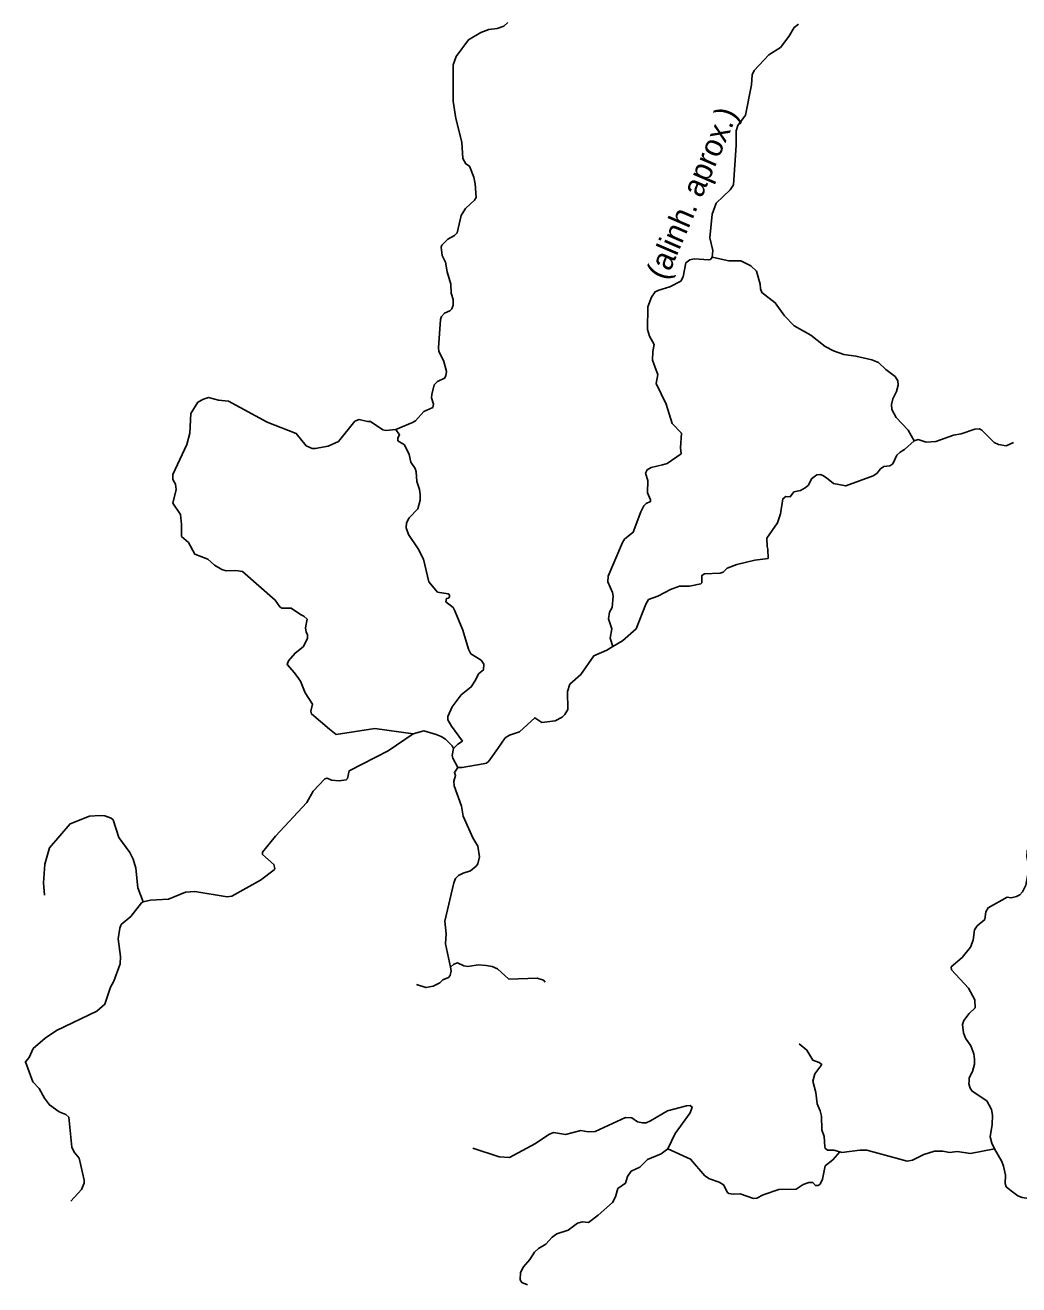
# Model space of a CAD drawing. Extents: x 332 to 501, y 9447 to 9559.
# Drawn here: x 427.75 to 444.61, y 9511.96 to 9533.34 of the extents above; entities that cross this region are included whole.
import ezdxf

# ---------------------------------------------------------------- set-up
doc = ezdxf.new("R2010")
doc.units = 0
for name, color, linetype in [('Level 31', 7, 'Continuous'), ('Level 5', 7, 'Continuous'), ('Level 6', 7, 'Continuous'), ('Level 7', 7, 'Continuous')]:
    doc.layers.add(name, color=color, linetype=linetype)

msp = doc.modelspace()

# ---------------------------------------------------------------- linework, layer by layer
at = {"layer": 'Level 5'}
for points in [[(435.3981, 9530.4192), (435.3855, 9530.6514), (435.3615, 9530.7649), (435.2848, 9530.9504), (435.2256, 9530.9888), (435.1712, 9531.0831), (435.1588, 9531.3603), (435.0561, 9531.7611), (435.0109, 9532.0528), (435.0114, 9532.6725), (435.0625, 9532.8116), (435.272, 9533.0962), (435.4783, 9533.2193), (435.6142, 9533.2689), (435.7565, 9533.2897), (435.8684, 9533.3265), (435.9372, 9533.392)], [(440.8715, 9533.3618), (440.7932, 9533.3049), (440.7043, 9533.1511), (440.5631, 9532.9666), (440.3647, 9532.8404), (440.1169, 9532.5734), (440.0833, 9532.503), (440.0705, 9532.3303), (439.9706, 9531.8193), (439.8404, 9531.6404), (439.8116, 9531.5481), (439.8131, 9531.307), (439.7667, 9530.6354), (439.7091, 9530.5507), (439.4725, 9530.3252), (439.4021, 9530.1365), (439.3669, 9529.7336), (439.4158, 9529.5186), (439.4053, 9529.4058)], [(435.0089, 9528.6887), (434.9746, 9528.7966), (434.9698, 9528.9501), (434.9064, 9529.1581), (434.88, 9529.32), (434.8246, 9529.4335), (434.8067, 9529.5753), (434.8195, 9529.6073), (434.9202, 9529.7112), (435.0306, 9529.7726), (435.0793, 9529.8183), (435.1463, 9530.1146), (435.2192, 9530.2293), (435.3711, 9530.3716), (435.3981, 9530.4192)], [(439.1012, 9529.3791), (439.028, 9529.3626), (438.9592, 9529.3115), (438.9106, 9529.0735), (438.8727, 9528.9973), (438.6858, 9528.9005), (438.4979, 9528.8473)], [(439.3751, 9529.3684), (439.3494, 9529.3578), (439.1012, 9529.3791)], [(439.4053, 9529.4058), (439.3751, 9529.3684)], [(438.4979, 9528.8473), (438.4347, 9528.819), (438.3756, 9528.7262), (438.3132, 9528.5631), (438.3084, 9528.1794), (438.3404, 9528.0643), (438.4201, 9527.9247), (438.3964, 9527.8068), (438.3927, 9527.6598), (438.4539, 9527.4855)], [(434.0394, 9526.482), (434.3222, 9526.598), (434.3718, 9526.6284), (434.5125, 9526.7835), (434.6628, 9526.8538), (434.6756, 9526.9098), (434.6436, 9527.0185), (434.6468, 9527.0729), (434.6868, 9527.236), (434.7411, 9527.2952), (434.8642, 9527.3527), (434.8866, 9527.3927), (434.8946, 9527.4631), (434.8515, 9527.6357), (434.7667, 9527.8084), (434.7587, 9527.866), (434.7939, 9528.3489), (434.8115, 9528.4001), (434.8627, 9528.4544), (434.9522, 9528.4944), (434.9842, 9528.5296), (435.0114, 9528.5919), (435.0089, 9528.6887)], [(438.4539, 9527.4855), (438.4835, 9527.4163), (438.4539, 9527.2581), (438.6219, 9526.912), (438.7278, 9526.5821), (438.8815, 9526.42), (438.8645, 9526.1706), (438.8805, 9526.0683), (438.6401, 9525.9007), (438.5624, 9525.8806), (438.3692, 9525.8369), (438.302, 9525.7953), (438.2748, 9525.741), (438.3116, 9525.6115), (438.3084, 9525.4068), (438.3596, 9525.2869), (438.358, 9525.2549), (438.2845, 9525.2213), (438.2461, 9525.1845), (438.1933, 9525.0838), (438.0638, 9524.7352), (437.9167, 9524.6153), (437.8831, 9524.5641), (437.6417, 9523.9916), (437.6344, 9523.8938), (437.7136, 9523.715), (437.726, 9523.6512), (437.7072, 9523.4559), (437.6624, 9523.3792), (437.6465, 9523.2673), (437.7008, 9523.0978), (437.672, 9522.9347), (437.7204, 9522.7964)], [(434.0394, 9526.482), (433.8697, 9526.4605), (433.8185, 9526.4749), (433.6059, 9526.6172), (433.5563, 9526.6156), (433.4124, 9526.6508), (433.3436, 9526.6236), (433.0634, 9526.2744), (432.8879, 9526.1983), (432.6705, 9526.1567), (432.6161, 9526.1599), (432.517, 9526.2031), (432.3468, 9526.4096), (431.8543, 9526.6032), (431.1978, 9526.9594), (431.0299, 9526.9802), (430.8572, 9527.0249), (430.7712, 9526.9959)], [(435.1661, 9521.1906), (434.981, 9521.4444), (434.9202, 9521.5532), (434.9186, 9521.6075), (434.9906, 9521.7706), (435.1457, 9521.9769), (435.3152, 9522.1096), (435.3903, 9522.2215), (435.4367, 9522.3303), (435.523, 9522.399), (435.5294, 9522.4934), (435.4831, 9522.5653), (435.312, 9522.674), (435.2688, 9522.7492), (435.1744, 9523.0754), (435.0369, 9523.4016), (435.0081, 9523.4559), (434.8866, 9523.5535), (434.8956, 9523.6095), (434.9329, 9523.6173), (434.9496, 9523.639), (434.9467, 9523.6704), (434.9247, 9523.6896), (434.7445, 9523.7166), (434.5972, 9523.8941), (434.5077, 9524.2811), (434.4149, 9524.4538), (434.2518, 9524.6968), (434.2135, 9524.812), (434.2151, 9524.8967), (434.2646, 9524.9815), (434.4101, 9525.1334), (434.4485, 9525.2821), (434.449, 9525.3749), (434.4378, 9525.4639), (434.391, 9525.5987), (434.3814, 9525.7618), (434.3622, 9525.8161), (434.2934, 9525.9264), (434.2614, 9526.056), (434.1863, 9526.2191), (434.0687, 9526.2894), (434.0707, 9526.3405), (434.1017, 9526.392), (434.0394, 9526.482)], [(440.3401, 9524.4914), (440.3308, 9524.6322), (440.5118, 9524.8951), (440.5646, 9525.0486), (440.6045, 9525.3045), (440.6522, 9525.3423)], [(440.3482, 9524.4496), (440.3401, 9524.4914)], [(440.3554, 9524.2921), (440.3482, 9524.4496)], [(437.7204, 9522.7964), (437.8801, 9522.8921), (438.1136, 9523.096), (438.2764, 9523.5167), (438.326, 9523.5918), (438.4827, 9523.6478), (438.6986, 9523.7661), (438.8521, 9523.8221), (439.0184, 9523.8189), (439.2143, 9523.8608), (439.228, 9523.8766), (439.2315, 9524.0019), (439.2747, 9524.0284), (439.5396, 9524.0428), (439.5892, 9524.0571), (439.6596, 9524.1275), (439.8211, 9524.1884), (440.1265, 9524.2587), (440.3554, 9524.2921)], [(435.765, 9521.0613), (435.8943, 9521.2477), (435.9646, 9521.2895), (436.136, 9521.347), (436.3945, 9521.5851), (436.5155, 9521.5053), (436.74, 9521.5335), (436.8574, 9521.5939), (436.9045, 9521.6427), (436.9525, 9521.7274), (436.9477, 9522.0297), (436.9909, 9522.156), (437.178, 9522.3191), (437.3938, 9522.6389), (437.6177, 9522.7348), (437.7204, 9522.7964)], [(434.3317, 9521.3119), (434.5093, 9521.3645), (434.7204, 9521.3005), (434.8035, 9521.2701), (434.8786, 9521.2206), (434.9927, 9521.1115), (435.0147, 9521.0643)], [(433.0766, 9520.5138), (433.1965, 9520.5314), (433.2157, 9520.5554), (433.2462, 9520.6871), (433.9049, 9521.0271), (434.3317, 9521.3119)], [(435.0147, 9521.0643), (435.0865, 9521.1385), (435.1661, 9521.1906)], [(435.0152, 9521.0633), (434.9938, 9520.9456), (435.005, 9520.8976), (435.0881, 9520.7441)], [(435.0147, 9521.0643), (435.0152, 9521.0633)], [(435.5174, 9520.8057), (435.5742, 9520.816), (435.6126, 9520.8464), (435.765, 9521.0613)], [(435.0881, 9520.7441), (435.1617, 9520.7409), (435.5174, 9520.8057)], [(429.8723, 9518.4897), (430.1809, 9518.5079), (430.4686, 9518.6242), (430.6268, 9518.6374), (431.177, 9518.5439), (431.2554, 9518.5551), (431.7399, 9518.8285), (431.9712, 9519.0037), (431.9829, 9519.0273), (431.9658, 9519.0927), (431.775, 9519.2634), (431.7766, 9519.305), (431.9967, 9519.5769), (432.5266, 9520.1477), (432.6321, 9520.3395), (432.8304, 9520.549), (432.8735, 9520.5586), (432.9423, 9520.5266), (433.0766, 9520.5138)], [(427.7516, 9515.7433), (427.8145, 9515.819), (427.8815, 9515.968), (428.0861, 9516.1438), (428.2797, 9516.2782), (428.9643, 9516.6054), (429.0998, 9516.7225), (429.1943, 9517.0121), (429.2532, 9517.1147), (429.3574, 9517.4086), (429.3654, 9517.5302), (429.327, 9517.834), (429.351, 9518.0162), (429.3734, 9518.0738), (429.5397, 9518.2097), (429.7236, 9518.4464), (429.7496, 9518.4612)], [(429.7496, 9518.4612), (429.8723, 9518.4897)], [(427.7438, 9515.7339), (427.7516, 9515.7433)], [(427.7516, 9515.7433), (427.8797, 9515.4033), (427.9871, 9515.293), (428.0747, 9515.1283), (428.1579, 9515.0132), (428.3226, 9514.8949), (428.4377, 9514.8517), (428.4873, 9514.8069), (428.5368, 9514.2984), (428.5784, 9514.2089), (428.6648, 9514.1066), (428.7465, 9513.7377), (428.7461, 9513.6822), (428.7034, 9513.5784), (428.521, 9513.3792)]]:
    msp.add_lwpolyline(points, dxfattribs=at)
at = {"layer": 'Level 6'}
for points in [[(432.316, 9522.3506), (432.194, 9522.4886), (432.2148, 9522.5525), (432.3267, 9522.6836), (432.4642, 9522.7908), (432.5378, 9522.9299), (432.5378, 9523.0018), (432.5138, 9523.037), (432.5042, 9523.1154), (432.5298, 9523.2593), (432.4774, 9523.3124), (432.4178, 9523.3376), (432.2627, 9523.4479), (432.1012, 9523.4463), (432.0661, 9523.4687), (431.9909, 9523.5839), (431.4365, 9524.0679), (431.3209, 9524.0859), (431.1578, 9524.0811), (431.0843, 9524.1003), (430.9612, 9524.1787), (430.8444, 9524.2778), (430.6238, 9524.3611), (430.5183, 9524.5625), (430.3999, 9524.6633), (430.4015, 9524.8695), (430.3807, 9525.039), (430.25, 9525.2302), (430.3116, 9525.4639), (430.2967, 9525.5505), (430.2512, 9525.6306), (430.2512, 9525.717), (430.4927, 9526.227), (430.5417, 9526.4204), (430.5567, 9526.7507), (430.6773, 9526.9434), (430.7712, 9526.9959)], [(432.909, 9521.3916), (432.6033, 9521.6523), (432.5953, 9521.6987), (432.6225, 9521.8154), (432.4962, 9522.0073), (432.4165, 9522.2053), (432.316, 9522.3506)], [(434.3317, 9521.3119), (433.681, 9521.4029), (433.0254, 9521.3005), (432.909, 9521.3916)], [(429.7496, 9518.4612), (429.6564, 9518.7006), (429.6244, 9519.0332), (429.5813, 9519.1851), (429.5253, 9519.2986), (429.3382, 9519.5545), (429.2375, 9519.8519), (429.2071, 9519.8806), (429.1, 9519.919), (429.0152, 9519.9286), (428.8393, 9519.9126), (428.5084, 9519.7831), (428.1597, 9519.3802), (428.0829, 9519.1004), (428.0557, 9518.7806), (428.0723, 9518.5732)]]:
    msp.add_lwpolyline(points, dxfattribs=at)
at = {"layer": 'Level 7'}
for points in [[(439.4053, 9529.4058), (439.688, 9529.3455), (439.8923, 9529.3446), (440.0577, 9529.2561), (440.1581, 9529.1696), (440.2204, 9528.9489), (440.2236, 9528.8674), (440.2444, 9528.8034), (440.4747, 9528.6323), (440.633, 9528.4085), (440.7977, 9528.2406), (441.0791, 9528.0807), (441.3209, 9527.8888), (441.4612, 9527.8137), (441.6387, 9527.7545), (441.845, 9527.7257), (442.1131, 9527.6641), (442.2252, 9527.6179), (442.3535, 9527.4971), (442.507, 9527.3819), (442.5555, 9527.308), (442.5598, 9527.2322), (442.5325, 9527.1277), (442.4686, 9526.9982), (442.4462, 9526.9038), (442.4558, 9526.8191), (442.5293, 9526.6848), (442.7289, 9526.4701), (442.831, 9526.2868)], [(442.831, 9526.2868), (442.8997, 9526.3076), (443.033, 9526.2659), (443.2025, 9526.2786), (443.5015, 9526.3826), (443.6294, 9526.4082), (443.8589, 9526.4843), (443.94, 9526.4886), (443.9816, 9526.4694), (444.1891, 9526.2579), (444.261, 9526.2275), (444.3937, 9526.2051), (444.5161, 9526.2615)], [(442.831, 9526.2868), (442.6672, 9526.1391), (442.5921, 9526.0975), (442.5361, 9526.0448), (442.469, 9525.8945), (442.421, 9525.8657), (442.3187, 9525.8497), (442.2611, 9525.8097), (442.1965, 9525.7313), (442.1348, 9525.693), (441.6711, 9525.5219), (441.4648, 9525.5619), (441.3467, 9525.6565)], [(441.3467, 9525.6565), (441.2841, 9525.701), (441.2378, 9525.7154), (441.1786, 9525.7106), (441.0922, 9525.6418), (441.0411, 9525.5363), (440.9819, 9525.4899), (440.9052, 9525.4452), (440.7916, 9525.4196), (440.7293, 9525.338), (440.6522, 9525.3423)], [(435.0881, 9520.7441), (435.0321, 9520.6545), (435.0497, 9520.6034), (435.0226, 9520.5074), (435.0289, 9520.4275), (435.1521, 9520.0853), (435.1773, 9519.9137), (435.3439, 9519.5465), (435.4255, 9519.4042), (435.4575, 9519.2251), (435.4255, 9519.1035), (435.4015, 9519.0684), (435.3056, 9518.9868), (435.1809, 9518.95), (435.0993, 9518.9069), (435.0513, 9518.8557), (435.021, 9518.7854), (434.8691, 9518.1346), (434.8898, 9517.9171), (434.8771, 9517.7492), (434.9643, 9517.3521)], [(444.4768, 9518.5304), (444.5681, 9518.5497), (444.6266, 9518.5805), (444.6723, 9518.6292), (444.7278, 9518.7434), (444.7704, 9518.9897), (444.7674, 9519.1109), (444.7426, 9519.2311), (444.7515, 9519.3205), (444.8359, 9519.5002), (445.0552, 9519.7961), (445.1078, 9519.8955)], [(443.7628, 9515.4189), (443.7667, 9515.4723), (443.8217, 9515.5826), (443.8553, 9515.7041), (443.8569, 9515.7921), (443.8441, 9515.88), (443.7913, 9516.0159), (443.7034, 9516.1471), (443.6698, 9516.235), (443.6538, 9516.3789), (443.6746, 9516.4445), (443.7657, 9516.5628), (443.8681, 9516.6635), (443.8617, 9516.7946), (443.7513, 9516.9945), (443.4635, 9517.3079), (443.4571, 9517.3559), (443.6458, 9517.5142), (443.7897, 9517.6892), (443.8321, 9517.8114), (443.8553, 9517.9859), (443.9, 9518.0514), (444.0295, 9518.1618), (444.0471, 9518.2929), (444.0871, 9518.36), (444.4101, 9518.5407), (444.4768, 9518.5304)], [(434.9643, 9517.3521), (434.9762, 9517.2919), (434.9602, 9517.212), (434.9282, 9517.1768), (434.8323, 9517.1368), (434.7811, 9517.0872), (434.6692, 9517.0265), (434.5477, 9517.0057), (434.3878, 9517.055)], [(434.9643, 9517.3521), (435.0236, 9517.4041), (435.0833, 9517.4246), (435.1888, 9517.3719), (435.2544, 9517.3623), (435.4415, 9517.391), (435.5678, 9517.3815), (435.6733, 9517.3623), (435.7645, 9517.3255), (435.9564, 9517.148), (436.4344, 9517.1672), (436.5448, 9517.1336), (436.5707, 9517.0943)], [(440.8796, 9516.0479), (441.0127, 9515.9439), (441.1098, 9515.7729), (441.2218, 9515.7313), (441.2645, 9515.6978), (441.1482, 9515.5426), (441.1153, 9515.415), (441.161, 9515.2228), (441.1834, 9515.0294), (441.2377, 9514.9142), (441.2601, 9514.8247), (441.2633, 9514.5897), (441.3065, 9514.4745), (441.3145, 9514.3002), (441.3209, 9514.2763), (441.3625, 9514.2443), (441.4664, 9514.2427), (441.5697, 9514.216)], [(444.1946, 9514.266), (444.1479, 9514.3626), (444.1191, 9514.4729), (444.1543, 9514.6808), (444.1607, 9514.8407), (444.1447, 9514.935), (444.0663, 9515.0821), (443.815, 9515.2458), (443.7801, 9515.2996), (443.7593, 9515.3716), (443.7628, 9515.4189)], [(438.6507, 9514.2695), (438.7753, 9514.5273), (439.0328, 9514.8807), (439.0648, 9514.9766), (439.0318, 9515.0046), (438.9672, 9514.9958), (438.6474, 9514.9126), (438.3561, 9514.7413)], [(438.3561, 9514.7413), (438.2845, 9514.7112), (438.2221, 9514.7064), (438.1389, 9514.7272), (438.0398, 9514.7911), (437.9343, 9514.7975), (437.4194, 9514.5609), (437.2995, 9514.5561), (437.1764, 9514.5769), (436.9173, 9514.5129), (436.7095, 9514.5433), (436.6311, 9514.5097), (436.4057, 9514.3562), (435.9675, 9514.1196), (435.7885, 9514.1323), (435.3424, 9514.2779)], [(438.6507, 9514.2695), (438.5387, 9514.1819), (438.3052, 9514.0844), (438.1789, 9513.9549), (438.0302, 9513.8861), (437.9679, 9513.795), (437.9311, 9513.6846), (437.8048, 9513.5935), (437.7632, 9513.4496), (437.7104, 9513.3553), (437.4689, 9513.1434)], [(441.5697, 9514.216), (441.452, 9514.0828), (441.3241, 9513.9772), (441.2761, 9513.7518), (441.2393, 9513.6687), (441.2006, 9513.6456), (441.1603, 9513.6476), (441.1137, 9513.6932), (441.043, 9513.6952), (440.9512, 9513.6594), (440.828, 9513.5802), (440.5374, 9513.5759), (440.272, 9513.488), (440.1616, 9513.4288), (440.1057, 9513.4224), (439.8786, 9513.504), (439.7667, 9513.496), (439.6899, 9513.5088), (439.6628, 9513.5247), (439.5956, 9513.6559), (439.5221, 9513.7006), (439.3574, 9513.7582), (439.279, 9513.811), (439.0392, 9514.0908), (438.6507, 9514.2695)], [(441.5697, 9514.216), (441.6053, 9514.2068), (441.9125, 9514.2459), (442.0292, 9514.2459), (442.712, 9514.0588), (442.8015, 9514.0732), (442.995, 9514.1707), (443.1757, 9514.2251), (443.3196, 9514.2267), (443.4331, 9514.2059), (443.5595, 9514.2203), (443.7897, 9514.1883), (444.1946, 9514.266)], [(444.1946, 9514.266), (444.319, 9514.0508), (444.3493, 9513.9709), (444.3813, 9513.8222), (444.3749, 9513.6782), (444.3957, 9513.6223), (444.4801, 9513.556)], [(446.4015, 9513.1554), (446.2625, 9513.1514), (446.1464, 9513.1027), (445.8377, 9513.0452), (445.7344, 9513.1038), (445.5816, 9513.2667), (445.4386, 9513.3829), (445.3017, 9513.4197), (445.1707, 9513.3899), (444.8768, 9513.409), (444.6664, 9513.4407), (444.59, 9513.4705), (444.4801, 9513.556)], [(437.3039, 9513.0165), (437.2027, 9513.0263), (437.1201, 9513.0029), (436.9602, 9512.8862), (436.7667, 9512.8238), (436.69, 9512.7694), (436.5844, 9512.6463), (436.4581, 9512.5728), (436.391, 9512.5152), (436.311, 9512.3905), (436.2055, 9512.2658), (436.1527, 9512.165), (436.1447, 9512.0419), (436.1719, 9511.9971), (436.271, 9511.9588)], [(437.4689, 9513.1434), (437.3039, 9513.0165)]]:
    msp.add_lwpolyline(points, dxfattribs=at)

# ---------------------------------------------------------------- texts
at = {"layer": 'Level 31'}
msp.add_text('(alinh. aprox.)', height=0.38, rotation=66.73437, dxfattribs=at).set_placement((438.6216, 9528.9967))

doc.saveas('drawing.dxf')
